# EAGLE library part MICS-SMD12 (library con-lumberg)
CONNECTOR
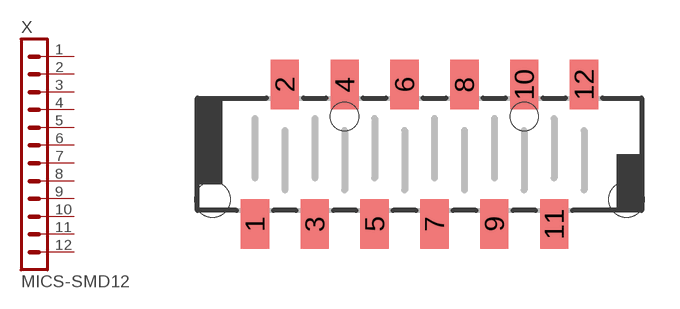
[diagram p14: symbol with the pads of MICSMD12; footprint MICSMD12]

Designator prefix X

## MICS-SMD12 (OC_FARNELL: unknown; OC_NEWARK: unknown)  [MICSMD12]
1  1  pas
2  2  pas
3  3  pas
4  4  pas
5  5  pas
6  6  pas
7  7  pas
8  8  pas
9  9  pas
10  10  pas
11  11  pas
12  12  pas

## Footprint MICSMD12 (pad centres in mm)
CONNECTOR
smd 1.2 x 2.1: 1 -6.985,-2.959; 2 -5.715,2.959; 3 -4.445,-2.959; 4 -3.175,2.959; 5 -1.905,-2.959; 6 -0.635,2.959; 7 0.635,-2.959; 8 1.905,2.959; 9 3.175,-2.959; 10 4.445,2.959; 11 5.715,-2.959; 12 6.985,2.959
hole 1.5 at 8.785,-1.912
hole 1.5 at -8.785,-1.912
hole 1.2 at -3.175,1.6
hole 1.2 at 4.445,1.6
